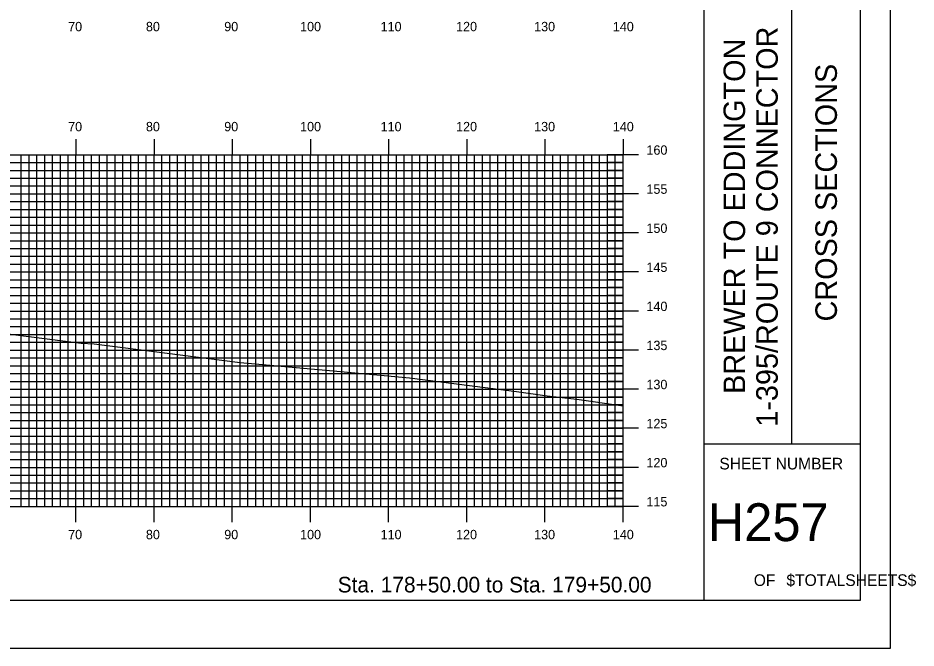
# Model space of a CAD drawing. Extents: x 1785402 to 1785745, y 442591 to 442811.
# Drawn here: x 1785630.1 to 1785745, y 442590.5 to 442671.2 of the extents above; entities that cross this region are included whole.
import ezdxf

# ---------------------------------------------------------------- set-up
doc = ezdxf.new("R2010")
doc.units = 0
for name, color, linetype in [('BORDER', 7, 'Continuous'), ('H_V ANNOTATION', 7, 'Continuous'), ('MAJOR', 7, 'Continuous'), ('MINOR', 7, 'Continuous'), ('PLOT BOUNDARY', 7, 'Continuous'), ('S_Roadway_Centerline', 7, 'Continuous')]:
    doc.layers.add(name, color=color, linetype=linetype)

msp = doc.modelspace()

# ---------------------------------------------------------------- linework, layer by layer
at = {"layer": 'BORDER'}
for p, q in [((1785717.94, 442596.67), (1785717.94, 442806.67)), ((1785729.12, 442616.67), (1785729.12, 442686.67)), ((1785729.12, 442616.67), (1785729.12, 442686.67)), ((1785717.94, 442616.67), (1785737.94, 442616.67)), ((1785717.94, 442616.67), (1785737.94, 442616.67))]:
    msp.add_line(p, q, dxfattribs=at)
msp.add_lwpolyline([(1785417.94, 442596.67), (1785737.94, 442596.67), (1785737.94, 442806.67), (1785417.94, 442806.67)], close=True, dxfattribs=at)
at = {"layer": 'MAJOR'}
for p, q in [((1785637.54, 442655.67), (1785637.54, 442653.67)), ((1785647.54, 442655.67), (1785647.54, 442653.67)), ((1785657.54, 442655.67), (1785657.54, 442653.67)), ((1785667.54, 442655.67), (1785667.54, 442653.67)), ((1785677.54, 442655.67), (1785677.54, 442653.67)), ((1785687.54, 442655.67), (1785687.54, 442653.67)), ((1785697.54, 442655.67), (1785697.54, 442653.67)), ((1785707.54, 442655.67), (1785707.54, 442653.67)), ((1785427.54, 442653.67), (1785707.54, 442653.67)), ((1785427.54, 442653.67), (1785707.54, 442653.67)), ((1785637.54, 442608.67), (1785637.54, 442653.67)), ((1785647.54, 442608.67), (1785647.54, 442653.67)), ((1785657.54, 442608.67), (1785657.54, 442653.67)), ((1785667.54, 442608.67), (1785667.54, 442653.67)), ((1785677.54, 442608.67), (1785677.54, 442653.67)), ((1785687.54, 442608.67), (1785687.54, 442653.67)), ((1785697.54, 442608.67), (1785697.54, 442653.67)), ((1785709.54, 442653.67), (1785705.53, 442653.67)), ((1785707.54, 442608.67), (1785707.54, 442653.67)), ((1785707.54, 442608.67), (1785707.54, 442653.67)), ((1785427.54, 442648.67), (1785707.54, 442648.67)), ((1785709.54, 442648.67), (1785705.53, 442648.67)), ((1785427.54, 442643.67), (1785707.54, 442643.67)), ((1785709.54, 442643.67), (1785705.53, 442643.67)), ((1785427.54, 442638.67), (1785707.54, 442638.67)), ((1785709.54, 442638.67), (1785705.53, 442638.67)), ((1785427.54, 442633.67), (1785707.54, 442633.67)), ((1785709.54, 442633.67), (1785705.53, 442633.67)), ((1785427.54, 442628.67), (1785707.54, 442628.67)), ((1785709.54, 442628.67), (1785705.53, 442628.67)), ((1785427.54, 442623.67), (1785707.54, 442623.67)), ((1785709.54, 442623.67), (1785705.53, 442623.67)), ((1785427.54, 442618.67), (1785707.54, 442618.67)), ((1785709.54, 442618.67), (1785705.53, 442618.67)), ((1785427.54, 442613.67), (1785707.54, 442613.67)), ((1785709.54, 442613.67), (1785705.53, 442613.67)), ((1785427.54, 442608.67), (1785707.54, 442608.67)), ((1785427.54, 442608.67), (1785707.54, 442608.67)), ((1785637.54, 442606.66), (1785637.54, 442608.67)), ((1785647.54, 442606.66), (1785647.54, 442608.67)), ((1785657.54, 442606.66), (1785657.54, 442608.67)), ((1785667.54, 442606.66), (1785667.54, 442608.67)), ((1785677.54, 442606.66), (1785677.54, 442608.67)), ((1785687.54, 442606.66), (1785687.54, 442608.67)), ((1785697.54, 442606.66), (1785697.54, 442608.67)), ((1785709.54, 442608.67), (1785705.53, 442608.67)), ((1785707.54, 442606.66), (1785707.54, 442608.67))]:
    msp.add_line(p, q, dxfattribs=at)
at = {"layer": 'MINOR'}
for p, q in [((1785427.54, 442652.67), (1785707.54, 442652.67)), ((1785630.54, 442608.67), (1785630.54, 442653.67)), ((1785631.54, 442608.67), (1785631.54, 442653.67)), ((1785632.54, 442608.67), (1785632.54, 442653.67)), ((1785633.54, 442608.67), (1785633.54, 442653.67)), ((1785634.54, 442608.67), (1785634.54, 442653.67)), ((1785635.54, 442608.67), (1785635.54, 442653.67)), ((1785636.54, 442608.67), (1785636.54, 442653.67)), ((1785638.54, 442608.67), (1785638.54, 442653.67)), ((1785639.54, 442608.67), (1785639.54, 442653.67)), ((1785640.54, 442608.67), (1785640.54, 442653.67)), ((1785641.54, 442608.67), (1785641.54, 442653.67)), ((1785642.54, 442608.67), (1785642.54, 442653.67)), ((1785643.54, 442608.67), (1785643.54, 442653.67)), ((1785644.54, 442608.67), (1785644.54, 442653.67)), ((1785645.54, 442608.67), (1785645.54, 442653.67)), ((1785646.54, 442608.67), (1785646.54, 442653.67)), ((1785648.54, 442608.67), (1785648.54, 442653.67)), ((1785649.54, 442608.67), (1785649.54, 442653.67)), ((1785650.54, 442608.67), (1785650.54, 442653.67)), ((1785651.54, 442608.67), (1785651.54, 442653.67)), ((1785652.54, 442608.67), (1785652.54, 442653.67)), ((1785653.54, 442608.67), (1785653.54, 442653.67)), ((1785654.54, 442608.67), (1785654.54, 442653.67)), ((1785655.54, 442608.67), (1785655.54, 442653.67)), ((1785656.54, 442608.67), (1785656.54, 442653.67)), ((1785658.54, 442608.67), (1785658.54, 442653.67)), ((1785659.54, 442608.67), (1785659.54, 442653.67)), ((1785660.54, 442608.67), (1785660.54, 442653.67)), ((1785661.54, 442608.67), (1785661.54, 442653.67)), ((1785662.54, 442608.67), (1785662.54, 442653.67)), ((1785663.54, 442608.67), (1785663.54, 442653.67)), ((1785664.54, 442608.67), (1785664.54, 442653.67)), ((1785665.54, 442608.67), (1785665.54, 442653.67)), ((1785666.54, 442608.67), (1785666.54, 442653.67)), ((1785668.54, 442608.67), (1785668.54, 442653.67)), ((1785669.54, 442608.67), (1785669.54, 442653.67)), ((1785670.54, 442608.67), (1785670.54, 442653.67)), ((1785671.54, 442608.67), (1785671.54, 442653.67)), ((1785672.54, 442608.67), (1785672.54, 442653.67)), ((1785673.54, 442608.67), (1785673.54, 442653.67)), ((1785674.54, 442608.67), (1785674.54, 442653.67)), ((1785675.54, 442608.67), (1785675.54, 442653.67)), ((1785676.54, 442608.67), (1785676.54, 442653.67)), ((1785678.54, 442608.67), (1785678.54, 442653.67)), ((1785679.54, 442608.67), (1785679.54, 442653.67)), ((1785680.54, 442608.67), (1785680.54, 442653.67)), ((1785681.54, 442608.67), (1785681.54, 442653.67)), ((1785682.54, 442608.67), (1785682.54, 442653.67)), ((1785683.54, 442608.67), (1785683.54, 442653.67)), ((1785684.54, 442608.67), (1785684.54, 442653.67)), ((1785685.54, 442608.67), (1785685.54, 442653.67)), ((1785686.54, 442608.67), (1785686.54, 442653.67)), ((1785688.54, 442608.67), (1785688.54, 442653.67)), ((1785689.54, 442608.67), (1785689.54, 442653.67)), ((1785690.54, 442608.67), (1785690.54, 442653.67)), ((1785691.54, 442608.67), (1785691.54, 442653.67)), ((1785692.54, 442608.67), (1785692.54, 442653.67)), ((1785693.54, 442608.67), (1785693.54, 442653.67)), ((1785694.54, 442608.67), (1785694.54, 442653.67)), ((1785695.54, 442608.67), (1785695.54, 442653.67)), ((1785696.54, 442608.67), (1785696.54, 442653.67)), ((1785698.54, 442608.67), (1785698.54, 442653.67)), ((1785699.54, 442608.67), (1785699.54, 442653.67)), ((1785700.54, 442608.67), (1785700.54, 442653.67)), ((1785701.54, 442608.67), (1785701.54, 442653.67)), ((1785702.54, 442608.67), (1785702.54, 442653.67)), ((1785703.54, 442608.67), (1785703.54, 442653.67)), ((1785704.54, 442608.67), (1785704.54, 442653.67)), ((1785707.54, 442652.67), (1785705.53, 442652.67)), ((1785705.54, 442608.67), (1785705.54, 442653.67)), ((1785706.54, 442608.67), (1785706.54, 442653.67)), ((1785427.54, 442651.67), (1785707.54, 442651.67)), ((1785707.54, 442651.67), (1785705.53, 442651.67)), ((1785427.54, 442650.67), (1785707.54, 442650.67)), ((1785707.54, 442650.67), (1785705.53, 442650.67)), ((1785427.54, 442649.67), (1785707.54, 442649.67)), ((1785707.54, 442649.67), (1785705.53, 442649.67)), ((1785427.54, 442647.67), (1785707.54, 442647.67)), ((1785707.54, 442647.67), (1785705.53, 442647.67)), ((1785427.54, 442646.67), (1785707.54, 442646.67)), ((1785427.54, 442645.67), (1785707.54, 442645.67)), ((1785707.54, 442646.67), (1785705.53, 442646.67)), ((1785707.54, 442645.67), (1785705.53, 442645.67)), ((1785427.54, 442644.67), (1785707.54, 442644.67)), ((1785707.54, 442644.67), (1785705.53, 442644.67)), ((1785427.54, 442642.67), (1785707.54, 442642.67)), ((1785707.54, 442642.67), (1785705.53, 442642.67)), ((1785427.54, 442641.67), (1785707.54, 442641.67)), ((1785707.54, 442641.67), (1785705.53, 442641.67)), ((1785427.54, 442640.67), (1785707.54, 442640.67)), ((1785707.54, 442640.67), (1785705.53, 442640.67)), ((1785427.54, 442639.67), (1785707.54, 442639.67)), ((1785707.54, 442639.67), (1785705.53, 442639.67)), ((1785427.54, 442637.67), (1785707.54, 442637.67)), ((1785707.54, 442637.67), (1785705.53, 442637.67)), ((1785427.54, 442636.67), (1785707.54, 442636.67)), ((1785707.54, 442636.67), (1785705.53, 442636.67)), ((1785427.54, 442635.67), (1785707.54, 442635.67)), ((1785707.54, 442635.67), (1785705.53, 442635.67)), ((1785427.54, 442634.67), (1785707.54, 442634.67)), ((1785707.54, 442634.67), (1785705.53, 442634.67)), ((1785427.54, 442632.67), (1785707.54, 442632.67)), ((1785707.54, 442632.67), (1785705.53, 442632.67)), ((1785427.54, 442631.67), (1785707.54, 442631.67)), ((1785707.54, 442631.67), (1785705.53, 442631.67)), ((1785427.54, 442630.67), (1785707.54, 442630.67)), ((1785427.54, 442629.67), (1785707.54, 442629.67)), ((1785707.54, 442630.67), (1785705.53, 442630.67)), ((1785707.54, 442629.67), (1785705.53, 442629.67)), ((1785427.54, 442627.67), (1785707.54, 442627.67)), ((1785707.54, 442627.67), (1785705.53, 442627.67)), ((1785427.54, 442626.67), (1785707.54, 442626.67)), ((1785707.54, 442626.67), (1785705.53, 442626.67)), ((1785427.54, 442625.67), (1785707.54, 442625.67)), ((1785707.54, 442625.67), (1785705.53, 442625.67)), ((1785427.54, 442624.67), (1785707.54, 442624.67)), ((1785707.54, 442624.67), (1785705.53, 442624.67)), ((1785427.54, 442622.67), (1785707.54, 442622.67)), ((1785707.54, 442622.67), (1785705.53, 442622.67)), ((1785427.54, 442621.67), (1785707.54, 442621.67)), ((1785707.54, 442621.67), (1785705.53, 442621.67)), ((1785427.54, 442620.67), (1785707.54, 442620.67)), ((1785707.54, 442620.67), (1785705.53, 442620.67)), ((1785427.54, 442619.67), (1785707.54, 442619.67)), ((1785707.54, 442619.67), (1785705.53, 442619.67)), ((1785427.54, 442617.67), (1785707.54, 442617.67)), ((1785707.54, 442617.67), (1785705.53, 442617.67)), ((1785427.54, 442616.67), (1785707.54, 442616.67)), ((1785707.54, 442616.67), (1785705.53, 442616.67)), ((1785427.54, 442615.67), (1785707.54, 442615.67)), ((1785427.54, 442614.67), (1785707.54, 442614.67)), ((1785707.54, 442615.67), (1785705.53, 442615.67)), ((1785707.54, 442614.67), (1785705.53, 442614.67)), ((1785427.54, 442612.67), (1785707.54, 442612.67)), ((1785707.54, 442612.67), (1785705.53, 442612.67)), ((1785427.54, 442611.67), (1785707.54, 442611.67)), ((1785707.54, 442611.67), (1785705.53, 442611.67)), ((1785427.54, 442610.67), (1785707.54, 442610.67)), ((1785707.54, 442610.67), (1785705.53, 442610.67)), ((1785427.54, 442609.67), (1785707.54, 442609.67)), ((1785707.54, 442609.67), (1785705.53, 442609.67))]:
    msp.add_line(p, q, dxfattribs=at)
at = {"layer": 'PLOT BOUNDARY'}
msp.add_lwpolyline([(1785401.75, 442590.55), (1785741.75, 442590.55), (1785741.75, 442810.55), (1785401.75, 442810.55)], close=True, dxfattribs=at)
at = {"layer": 'S_Roadway_Centerline'}
msp.add_lwpolyline([(1785618.76, 442632.05), (1785638.22, 442629.56), (1785639.87, 442629.46), (1785658.56, 442627.08), (1785669.5, 442626.09), (1785680.21, 442625.13), (1785693.93, 442623.39), (1785697.83, 442622.84), (1785701.64, 442622.4), (1785707.54, 442621.56)], dxfattribs=at)

# ---------------------------------------------------------------- texts
at = {"layer": 'BORDER'}
for s, p in [('1-395/ROUTE 9 CONNECTOR', (1785727.34, 442618.87)), ('BREWER TO EDDINGTON', (1785723.16, 442623.07)), ('CROSS SECTIONS', (1785734.91, 442632.34)), ('CROSS SECTIONS', (1785734.91, 442632.34))]:
    msp.add_text(s, height=2.7557, rotation=90, dxfattribs=at).set_placement(p)
for s, height, p in [('SHEET NUMBER', 1.4905, (1785719.87, 442613.4)), ('SHEET NUMBER', 1.4905, (1785719.87, 442613.4)), ('H257', 4.839, (1785718.38, 442604.23)), ('OF', 1.491, (1785724.27, 442598.49)), ('OF', 1.491, (1785724.27, 442598.49)), ('$TOTALSHEETS$', 1.4905, (1785728.45, 442598.49))]:
    msp.add_text(s, height=height, dxfattribs=at).set_placement(p)
at = {"layer": 'H_V ANNOTATION'}
for s, height, p in [('70', 1.2, (1785636.54, 442669.47)), ('80', 1.2, (1785646.49, 442669.47)), ('90', 1.2, (1785656.51, 442669.47)), ('100', 1.2, (1785666.22, 442669.47)), ('110', 1.2, (1785676.52, 442669.47)), ('120', 1.2, (1785686.18, 442669.47)), ('130', 1.2, (1785696.17, 442669.47)), ('140', 1.2, (1785706.24, 442669.47)), ('70', 1.2, (1785636.54, 442656.67)), ('80', 1.2, (1785646.49, 442656.67)), ('90', 1.2, (1785656.51, 442656.67)), ('100', 1.2, (1785666.22, 442656.67)), ('110', 1.2, (1785676.52, 442656.67)), ('120', 1.2, (1785686.18, 442656.67)), ('130', 1.2, (1785696.17, 442656.67)), ('140', 1.2, (1785706.24, 442656.67)), ('160', 1.2, (1785710.54, 442653.67)), ('155', 1.2, (1785710.54, 442648.67)), ('150', 1.2, (1785710.54, 442643.67)), ('145', 1.2, (1785710.54, 442638.67)), ('140', 1.2, (1785710.54, 442633.67)), ('135', 1.2, (1785710.54, 442628.67)), ('130', 1.2, (1785710.54, 442623.67)), ('125', 1.2, (1785710.54, 442618.67)), ('120', 1.2, (1785710.54, 442613.67)), ('115', 1.2, (1785710.54, 442608.67)), ('70', 1.2, (1785636.54, 442604.47)), ('80', 1.2, (1785646.49, 442604.47)), ('90', 1.2, (1785656.51, 442604.47)), ('100', 1.2, (1785666.22, 442604.47)), ('110', 1.2, (1785676.52, 442604.47)), ('120', 1.2, (1785686.18, 442604.47)), ('130', 1.2, (1785696.17, 442604.47)), ('140', 1.2, (1785706.24, 442604.47)), ('Sta. 178+50.00 to Sta. 179+50.00', 2.0004, (1785671.03, 442597.66))]:
    msp.add_text(s, height=height, dxfattribs=at).set_placement(p)

doc.saveas('drawing.dxf')
